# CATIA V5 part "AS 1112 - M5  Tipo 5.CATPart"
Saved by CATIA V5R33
Part number: AS 1112 - M5  Tipo 5
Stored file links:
  C:\Users\Ryzen5700u\Desktop\robot_cicloidale_singolo\Assieme_robot_cicloidale_singolo\AS 1112 - M5  Tipo 5.CATPart

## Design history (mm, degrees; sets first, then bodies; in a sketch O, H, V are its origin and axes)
Body1 "Solid1" (main body)
  Solid1: solid without history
